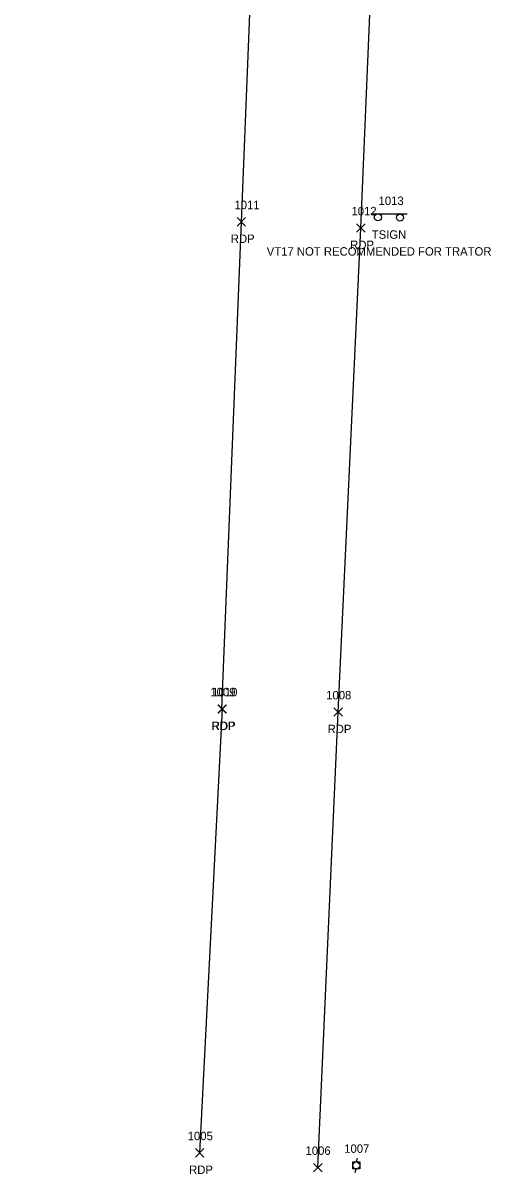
# Model space of a CAD drawing. Extents: x 1496556 to 1498241, y 599216 to 604470.
# Drawn here: x 1497213.5 to 1497324.3, y 601835.3 to 602108 of the extents above; entities that cross this region are included whole.
import ezdxf

# ---------------------------------------------------------------- set-up
doc = ezdxf.new("R2010")
doc.units = 0
for name, color, linetype in [('P_A', 7, 'Continuous'), ('P_I', 7, 'Continuous'), ('P_TIC', 7, 'Continuous'), ('PET', 7, 'Continuous'), ('S_A', 7, 'Continuous'), ('S_C', 7, 'Continuous'), ('S_I', 7, 'Continuous'), ('SSGN', 7, 'Continuous'), ('U_I', 7, 'Continuous'), ('UP', 7, 'Continuous')]:
    doc.layers.add(name, color=color, linetype=linetype)

msp = doc.modelspace()

# ---------------------------------------------------------------- linework, layer by layer
at = {"layer": 'P_TIC'}
for points in [[(1497264.21, 602059.91), (1497266.21, 602061.91)], [(1497266.21, 602059.91), (1497264.21, 602061.91)], [(1497292.47, 602058.45), (1497294.47, 602060.45)], [(1497294.47, 602058.45), (1497292.47, 602060.45)], [(1497259.6, 601944.5), (1497261.6, 601946.5)], [(1497261.6, 601944.5), (1497259.6, 601946.5)], [(1497259.72, 601944.51), (1497261.72, 601946.51)], [(1497261.72, 601944.51), (1497259.72, 601946.51)], [(1497287.13, 601943.77), (1497289.13, 601945.77)], [(1497289.13, 601943.77), (1497287.13, 601945.77)], [(1497254.35, 601839.33), (1497256.35, 601841.33)], [(1497256.35, 601839.33), (1497254.35, 601841.33)], [(1497282.3, 601835.85), (1497284.3, 601837.85)], [(1497284.3, 601835.85), (1497282.3, 601837.85)]]:
    msp.add_lwpolyline(points, dxfattribs=at)
at = {"layer": 'PET'}
for points in [[(1497255.35, 601840.33), (1497260.72, 601945.51), (1497260.6, 601945.5), (1497265.21, 602060.91), (1497267.76, 602124.12), (1497271.3, 602209.29), (1497274.95, 602307.82), (1497276.81, 602364.31), (1497278.84, 602406.87), (1497280.41, 602449.54), (1497282.45, 602505.14), (1497283.29, 602549.03), (1497283.31, 602599.78), (1497282.4, 602667.07), (1497280.87, 602701.36), (1497277.35, 602744.02), (1497266.99, 602833.93), (1497261.25, 602868.44), (1497249.2, 602924.4), (1497241.75, 602954.09), (1497234.18, 602981.9), (1497224.39, 603014.86), (1497221.77, 603020.8), (1497213.53, 603046.79)], [(1497283.3, 601836.85), (1497288.13, 601944.77), (1497293.47, 602059.45), (1497296.19, 602123.28), (1497299.59, 602207.66), (1497303.16, 602306.06), (1497305.27, 602361.72), (1497306.93, 602406.52), (1497308.5, 602446.65), (1497309.02, 602465.84), (1497310.76, 602505.51), (1497311.54, 602549.49), (1497311.88, 602599.1), (1497311.34, 602649.82), (1497308.95, 602706.57), (1497306.6, 602746.03), (1497301.66, 602792.87), (1497295.53, 602839.35), (1497290.13, 602872.5), (1497283.12, 602906.81), (1497277.08, 602932.51)]]:
    msp.add_lwpolyline(points, dxfattribs=at)
at = {"layer": 'SSGN'}
for p, q in [((1497295.86, 602062.82), (1497304.46, 602062.82)), ((1497299.88, 602061.91), (1497299.88, 602061.91))]:
    msp.add_line(p, q, dxfattribs=at)
for centre in [(1497297.52, 602061.98), (1497302.74, 602061.91)]:
    msp.add_circle(centre, 0.833, dxfattribs=at)
at = {"layer": 'UP'}
for p, q in [((1497291.57, 601836.51), (1497291.57, 601838.17)), ((1497291.57, 601838.17), (1497293.24, 601838.17)), ((1497292.65, 601839.01), (1497292.4, 601838.17)), ((1497292.4, 601837.34), (1497292.4, 601837.34)), ((1497293.24, 601838.17), (1497293.24, 601836.51)), ((1497293.24, 601836.51), (1497291.57, 601836.51)), ((1497292.15, 601835.67), (1497292.4, 601836.51))]:
    msp.add_line(p, q, dxfattribs=at)
msp.add_circle((1497292.4, 601837.34), 0.833, dxfattribs=at)

# ---------------------------------------------------------------- texts
at = {"layer": 'P_A'}
for p in [(1497262.7, 602055.91), (1497290.96, 602054.45), (1497258.09, 601940.5), (1497258.21, 601940.51), (1497285.61, 601939.77), (1497252.83, 601835.33)]:
    msp.add_text('RDP', height=2, dxfattribs=at).set_placement(p)
at = {"layer": 'P_I'}
for s, p in [('1011', (1497263.57, 602063.91)), ('1012', (1497291.26, 602062.45)), ('1009', (1497257.86, 601948.51)), ('1010', (1497258.31, 601948.5)), ('1008', (1497285.28, 601947.77)), ('1005', (1497252.5, 601843.33)), ('1006', (1497280.39, 601839.85))]:
    msp.add_text(s, height=2, dxfattribs=at).set_placement(p)
at = {"layer": 'S_A'}
msp.add_text('TSIGN', height=2, dxfattribs=at).set_placement((1497296.06, 602056.9))
at = {"layer": 'S_C'}
msp.add_text('VT17 NOT RECOMMENDED FOR TRATOR', height=2, dxfattribs=at).set_placement((1497271.21, 602052.9))
at = {"layer": 'S_I'}
msp.add_text('1013', height=2, dxfattribs=at).set_placement((1497297.67, 602064.9))
at = {"layer": 'U_I'}
msp.add_text('1007', height=2, dxfattribs=at).set_placement((1497289.55, 601840.34))

doc.saveas('drawing.dxf')
